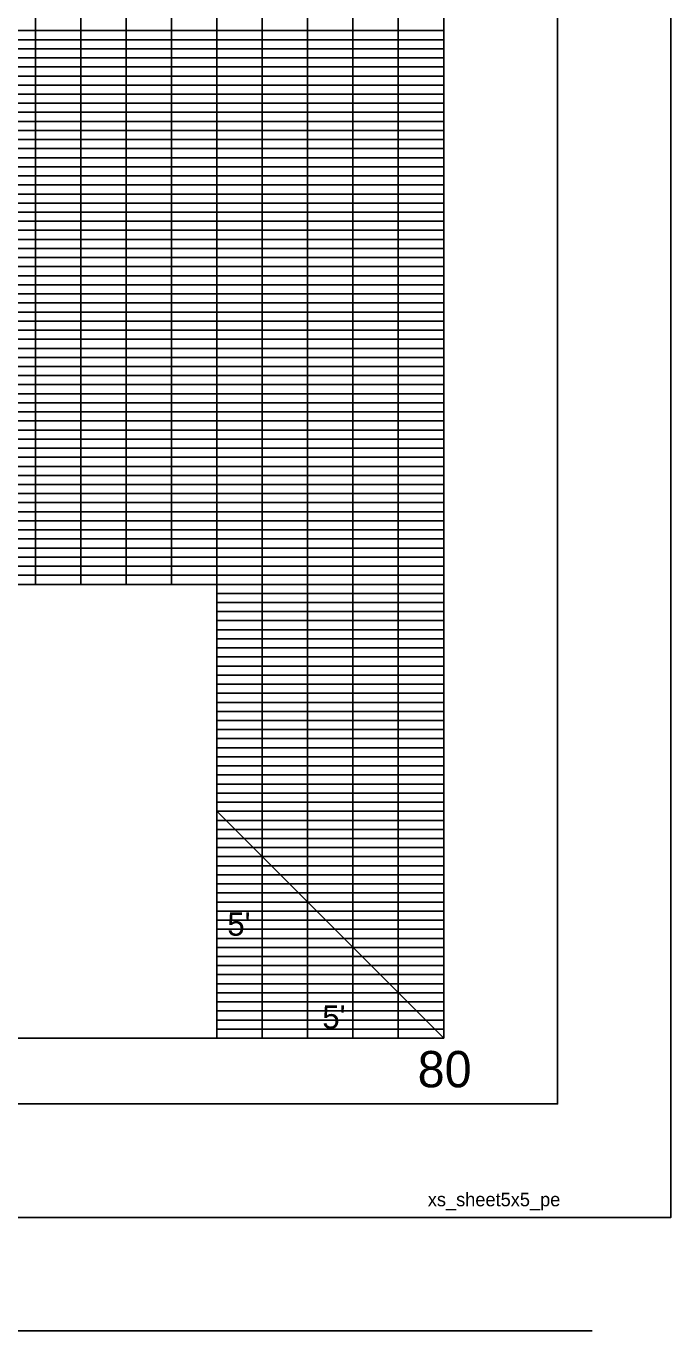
# Model space of a CAD drawing. Extents: x -15 to 165, y -6 to 109.
# Drawn here: x 150.79 to 165.01, y -6.45 to 22.3 of the extents above; entities that cross this region are included whole.
import ezdxf

# ---------------------------------------------------------------- set-up
doc = ezdxf.new("R2010")
doc.units = 0
for name, color, linetype in [('RD_SHT_Bndy', 7, 'Continuous'), ('RD_SHT_Iplotshp', 7, 'Continuous'), ('RD_SHT_MjGrid', 7, 'Continuous'), ('RD_SHT_MnGrid', 7, 'Continuous'), ('RD_SHT_SubGrid', 7, 'Continuous'), ('RD_SHT_TX', 7, 'Continuous')]:
    doc.layers.add(name, color=color, linetype=linetype)

msp = doc.modelspace()

# ---------------------------------------------------------------- linework, layer by layer
at = {"layer": 'RD_SHT_Bndy'}
for p, q in [((155, 5), (160, 0)), ((-12.73, -3.949), (163.27, -3.949)), ((-12.73, -6.449), (163.27, -6.449))]:
    msp.add_line(p, q, dxfattribs=at)
msp.add_lwpolyline([(-4.99, 103.551), (162.51, 103.551), (162.51, -1.449), (-4.99, -1.449)], close=True, dxfattribs=at)
at = {"layer": 'RD_SHT_Iplotshp'}
msp.add_lwpolyline([(-14.589, 106.051), (165.01, 106.051), (165.01, -3.949), (-14.589, -3.949)], close=True, dxfattribs=at)
at = {"layer": 'RD_SHT_MjGrid'}
for p, q in [((155, 0), (155, 100)), ((160, 0), (160, 100)), ((0, 20), (160, 20)), ((0, 15), (160, 15)), ((0, 10), (160, 10)), ((155, 5), (160, 5)), ((0, 0), (160, 0))]:
    msp.add_line(p, q, dxfattribs=at)
at = {"layer": 'RD_SHT_MnGrid'}
for p, q in [((151, 10), (151, 100)), ((152, 10), (152, 100)), ((153, 10), (153, 100)), ((154, 10), (154, 100)), ((156, 0), (156, 100)), ((157, 0), (157, 100)), ((158, 0), (158, 100)), ((159, 0), (159, 100)), ((0, 22), (160, 22)), ((0, 21), (160, 21)), ((0, 19), (160, 19)), ((0, 18), (160, 18)), ((0, 17), (160, 17)), ((0, 16), (160, 16)), ((0, 14), (160, 14)), ((0, 13), (160, 13)), ((0, 12), (160, 12)), ((0, 11), (160, 11)), ((155, 9), (160, 9)), ((155, 8), (160, 8)), ((155, 7), (160, 7)), ((155, 6), (160, 6)), ((155, 4), (160, 4)), ((155, 3), (160, 3)), ((155, 2), (160, 2)), ((155, 1), (160, 1))]:
    msp.add_line(p, q, dxfattribs=at)
at = {"layer": 'RD_SHT_SubGrid'}
for p, q in [((0, 22.2), (160, 22.2)), ((0, 21.8), (160, 21.8)), ((0, 21.6), (160, 21.6)), ((0, 21.4), (160, 21.4)), ((0, 21.2), (160, 21.2)), ((0, 20.8), (160, 20.8)), ((0, 20.6), (160, 20.6)), ((0, 20.4), (160, 20.4)), ((0, 20.2), (160, 20.2)), ((0, 19.8), (160, 19.8)), ((0, 19.6), (160, 19.6)), ((0, 19.4), (160, 19.4)), ((0, 19.2), (160, 19.2)), ((0, 18.8), (160, 18.8)), ((0, 18.6), (160, 18.6)), ((0, 18.4), (160, 18.4)), ((0, 18.2), (160, 18.2)), ((0, 17.8), (160, 17.8)), ((0, 17.6), (160, 17.6)), ((0, 17.4), (160, 17.4)), ((0, 17.2), (160, 17.2)), ((0, 16.8), (160, 16.8)), ((0, 16.6), (160, 16.6)), ((0, 16.4), (160, 16.4)), ((0, 16.2), (160, 16.2)), ((0, 15.8), (160, 15.8)), ((0, 15.6), (160, 15.6)), ((0, 15.4), (160, 15.4)), ((0, 15.2), (160, 15.2)), ((0, 14.8), (160, 14.8)), ((0, 14.6), (160, 14.6)), ((0, 14.4), (160, 14.4)), ((0, 14.2), (160, 14.2)), ((0, 13.8), (160, 13.8)), ((0, 13.6), (160, 13.6)), ((0, 13.4), (160, 13.4)), ((0, 13.2), (160, 13.2)), ((0, 12.8), (160, 12.8)), ((0, 12.6), (160, 12.6)), ((0, 12.4), (160, 12.4)), ((0, 12.2), (160, 12.2)), ((0, 11.8), (160, 11.8)), ((0, 11.6), (160, 11.6)), ((0, 11.4), (160, 11.4)), ((0, 11.2), (160, 11.2)), ((0, 10.8), (160, 10.8)), ((0, 10.6), (160, 10.6)), ((0, 10.4), (160, 10.4)), ((0, 10.2), (160, 10.2)), ((155, 9.8), (160, 9.8)), ((155, 9.6), (160, 9.6)), ((155, 9.4), (160, 9.4)), ((155, 9.2), (160, 9.2)), ((155, 8.8), (160, 8.8)), ((155, 8.6), (160, 8.6)), ((155, 8.4), (160, 8.4)), ((155, 8.2), (160, 8.2)), ((155, 7.8), (160, 7.8)), ((155, 7.6), (160, 7.6)), ((155, 7.4), (160, 7.4)), ((155, 7.2), (160, 7.2)), ((155, 6.8), (160, 6.8)), ((155, 6.6), (160, 6.6)), ((155, 6.4), (160, 6.4)), ((155, 6.2), (160, 6.2)), ((155, 5.8), (160, 5.8)), ((155, 5.6), (160, 5.6)), ((155, 5.4), (160, 5.4)), ((155, 5.2), (160, 5.2)), ((155, 5), (160, 5)), ((155, 4.8), (160, 4.8)), ((155, 4.6), (160, 4.6)), ((155, 4.4), (160, 4.4)), ((155, 4.2), (160, 4.2)), ((155, 3.8), (160, 3.8)), ((155, 3.6), (160, 3.6)), ((155, 3.4), (160, 3.4)), ((155, 3.2), (160, 3.2)), ((155, 2.8), (160, 2.8)), ((155, 2.6), (160, 2.6)), ((155, 2.4), (160, 2.4)), ((155, 2.2), (160, 2.2)), ((155, 1.8), (160, 1.8)), ((155, 1.6), (160, 1.6)), ((155, 1.4), (160, 1.4)), ((155, 1.2), (160, 1.2)), ((155, 0.8), (160, 0.8)), ((155, 0.6), (160, 0.6)), ((155, 0.4), (160, 0.4)), ((155, 0.2), (160, 0.2))]:
    msp.add_line(p, q, dxfattribs=at)

# ---------------------------------------------------------------- texts
at = {"layer": 'RD_SHT_TX'}
for s, height, p in [("5'", 0.512, (155.231, 2.258)), ("5'", 0.512, (157.325, 0.211)), ('80', 0.8, (159.426, -1.082)), ('xs_sheet5x5_pe', 0.3, (159.65, -3.704))]:
    msp.add_text(s, height=height, dxfattribs=at).set_placement(p)

doc.saveas('drawing.dxf')
